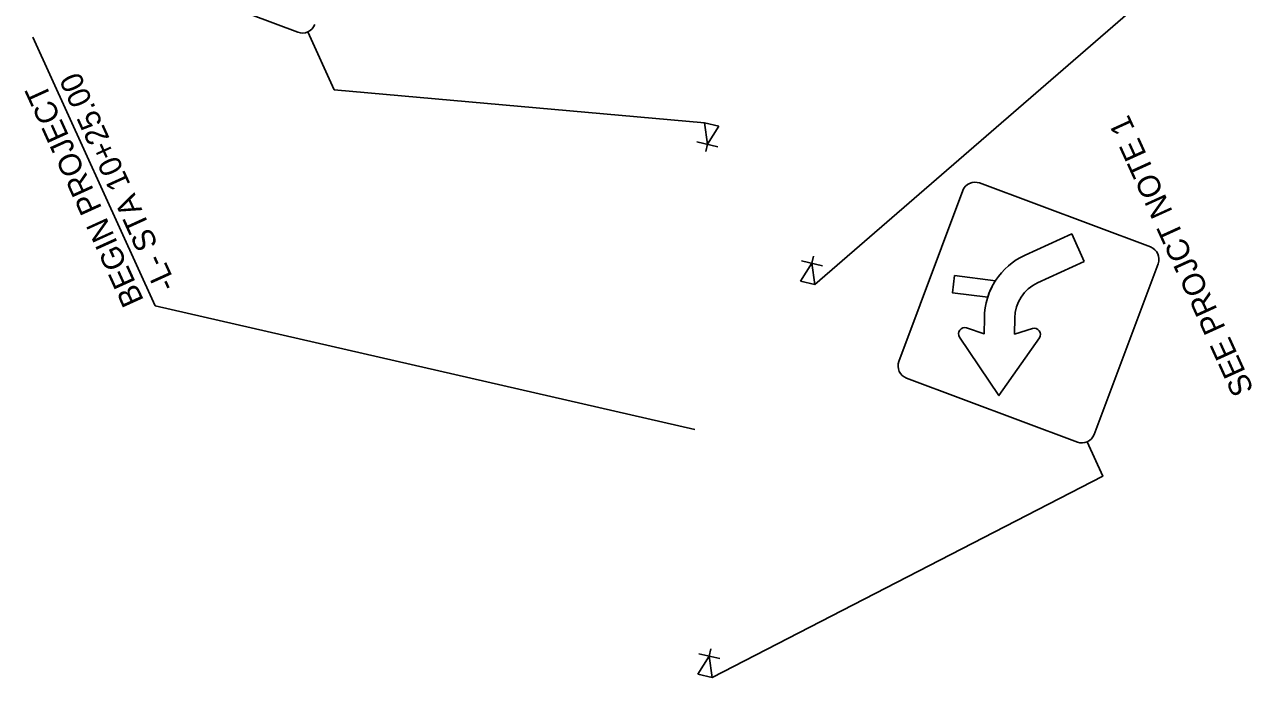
# Model space of a CAD drawing. Extents: x 2096999 to 2102576, y 682920 to 687015.
# Drawn here: x 2101912.2 to 2102297.6, y 682919.8 to 683124.6 of the extents above; entities that cross this region are included whole.
import ezdxf

# ---------------------------------------------------------------- set-up
doc = ezdxf.new("R2010")
doc.units = 0
doc.layers.add('Default', color=7, linetype='Continuous')
doc.layers.add('Prop Horizontal Alignment Station Label', color=7, linetype='Continuous')

msp = doc.modelspace()

# ---------------------------------------------------------------- linework, layer by layer
at = {"layer": 'Default'}
for p, q in [((2101944.35, 683142.33), (2101997.94, 683122.25)), ((2102126.35, 683087.09), (2102125.45, 683093.77)), ((2102125.45, 683093.77), (2102129.9, 683092.72)), ((2102129.9, 683092.72), (2102126.35, 683087.09)), ((2102123.02, 683087.88), (2102129.64, 683086.32)), ((2102126.35, 683087.09), (2102125.82, 683084.84)), ((2102206.45, 683072.54), (2102186.37, 683018.95)), ((2102265.29, 683054.85), (2102211.7, 683074.93)), ((2102155.55, 683044.11), (2102159.09, 683049.75)), ((2102162.43, 683048.97), (2102155.8, 683050.51)), ((2102159.09, 683049.75), (2102159.61, 683052)), ((2102159.09, 683049.75), (2102160, 683043.07)), ((2102244.51, 683050.27), (2102229.9, 683043.62)), ((2102244.51, 683050.27), (2102229.9, 683043.62)), ((2102244.51, 683050.27), (2102229.9, 683043.62)), ((2102247.6, 682996.01), (2102267.68, 683049.6)), ((2102160, 683043.07), (2102155.55, 683044.11)), ((2102188.76, 683013.7), (2102242.35, 682993.62)), ((2102245.47, 682993.72), (2102250.38, 682982.93)), ((2102123.37, 682920.83), (2102126.9, 682926.47)), ((2102130.24, 682925.69), (2102123.62, 682927.24)), ((2102126.9, 682926.47), (2102127.43, 682928.73)), ((2102126.9, 682926.47), (2102127.82, 682919.79)), ((2102127.82, 682919.79), (2102123.37, 682920.83))]:
    msp.add_line(p, q, dxfattribs=at)
for points in [[(2102256.81, 683142.95), (2102262.01, 683131.51), (2102160, 683043.07)], [(2102001.06, 683122.36), (2102009.32, 683104.2), (2102125.45, 683093.77)], [(2102225.96, 683052.29), (2102240.57, 683058.94), (2102244.51, 683050.27)], [(2102225.96, 683052.29), (2102240.57, 683058.94), (2102244.51, 683050.27)], [(2102225.96, 683052.29), (2102240.57, 683058.94), (2102244.51, 683050.27)], [(2102216.68, 683044.28), (2102203.86, 683045.88), (2102203.19, 683040.47), (2102214.23, 683039.1)], [(2102207.56, 683029.45), (2102213.16, 683027.62), (2102213.2, 683032.66)], [(2102207.56, 683029.45), (2102213.16, 683027.62), (2102213.2, 683032.66)], [(2102207.56, 683029.45), (2102213.16, 683027.62), (2102213.2, 683032.66)], [(2102222.73, 683032.58), (2102222.69, 683027.54), (2102228.31, 683029.27)], [(2102222.73, 683032.58), (2102222.69, 683027.54), (2102228.31, 683029.27)], [(2102222.73, 683032.58), (2102222.69, 683027.54), (2102228.31, 683029.27)], [(2102230.44, 683026.36), (2102217.76, 683008.21), (2102205.39, 683026.57)], [(2102230.44, 683026.36), (2102217.76, 683008.21), (2102205.39, 683026.57)], [(2102230.44, 683026.36), (2102217.76, 683008.21), (2102205.39, 683026.57)], [(2102250.38, 682982.93), (2102250.38, 682982.93), (2102127.82, 682919.79)]]:
    msp.add_lwpolyline(points, dxfattribs=at)
for centre, radius, start, end in [((2101999.37, 683126.07), 4.08, 249.458, 339.458), ((2102210.27, 683071.11), 4.08, 69.458, 159.458), ((2102263.86, 683051.03), 4.08, 339.458, 69.458), ((2102234.97, 683032.48), 21.77, 147.1671, 162.2946), ((2102190.19, 683017.52), 4.08, 159.458, 249.458), ((2102243.78, 682997.44), 4.08, 249.458, 339.458)]:
    msp.add_arc(centre, radius, start, end, dxfattribs=at)
for centre, major_axis, start_param, end_param in [((2102234.97, 683032.48), (-19.82, -9.01), 4.712389, 5.847944), ((2102234.97, 683032.48), (-19.82, -9.01), 4.712389, 5.847944), ((2102234.97, 683032.48), (-19.82, -9.01), 4.712389, 5.847944), ((2102234.97, 683032.48), (-11.15, -5.07), 4.712389, 5.847944), ((2102234.97, 683032.48), (-11.15, -5.07), 4.712389, 5.847944), ((2102234.97, 683032.48), (-11.15, -5.07), 4.712389, 5.847944), ((2102206.97, 683027.64), (-1.73, -0.79), 3.969953, 6.449197), ((2102206.97, 683027.64), (-1.73, -0.79), 3.969953, 6.449197), ((2102206.97, 683027.64), (-1.73, -0.79), 3.969953, 6.449197), ((2102228.87, 683027.45), (1.73, 0.79), 5.246691, 7.725935), ((2102228.87, 683027.45), (1.73, 0.79), 5.246691, 7.725935), ((2102228.87, 683027.45), (1.73, 0.79), 5.246691, 7.725935)]:
    msp.add_ellipse(centre, major_axis=major_axis, ratio=0.999989, start_param=start_param, end_param=end_param, dxfattribs=at)
at = {"layer": 'Prop Horizontal Alignment Station Label'}
for p, q in [((2101953.16, 683036.44), (2101914.83, 683120.69)), ((2102122.36, 682997.56), (2101953.16, 683036.44))]:
    msp.add_line(p, q, dxfattribs=at)

# ---------------------------------------------------------------- texts
at = {"layer": 'Default'}
msp.add_text('SEE PROJCT NOTE 1', height=7, rotation=114.4888, dxfattribs=at).set_placement((2102297.8, 683010.04))
at = {"layer": 'Prop Horizontal Alignment Station Label'}
for s, p in [('-L- STA 10+25.00', (2101959.98, 683042.76)), ('BEGIN PROJECT', (2101949.73, 683038.09))]:
    msp.add_text(s, height=7, rotation=114.458, dxfattribs=at).set_placement(p)

doc.saveas('drawing.dxf')
